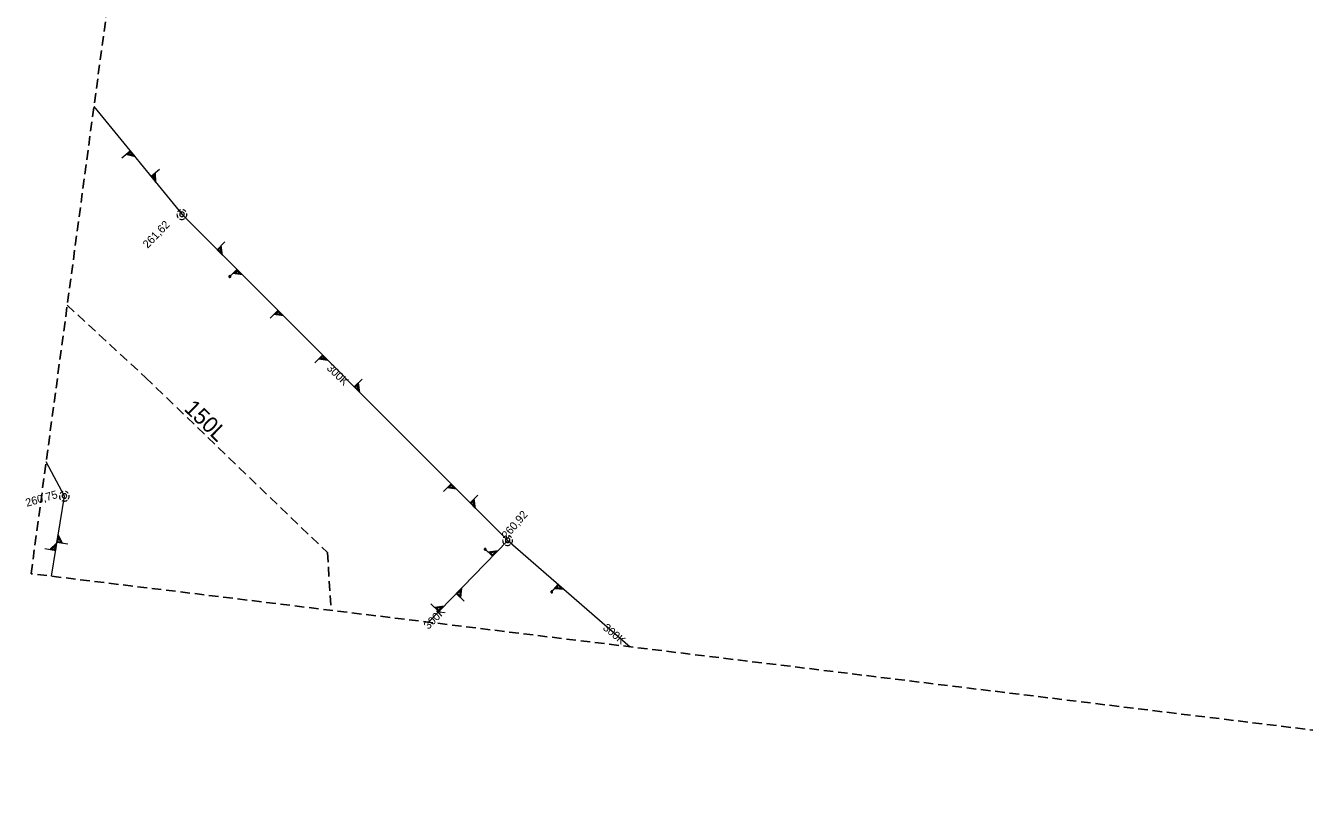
# Model space of a CAD drawing. Extents: x -743212 to -743020, y -1051380 to -1051228.
# Drawn here: x -743212.3 to -743084.5, y -1051380.3 to -1051304 of the extents above; entities that cross this region are included whole.
import ezdxf

# ---------------------------------------------------------------- set-up
doc = ezdxf.new("R2010")
doc.units = 0
doc.header["$LTSCALE"] = 0.32
doc.linetypes.add('MEDIUM_DASHED', pattern=[4.5, 3, -1.5])
for name, color, linetype, lineweight in [('1', 7, 'MEDIUM_DASHED', 25), ('18', 7, 'Continuous', 13), ('20', 7, 'Continuous', 13), ('8', 7, 'Continuous', 13)]:
    doc.layers.add(name, color=color, linetype=linetype, lineweight=lineweight)

msp = doc.modelspace()

# ---------------------------------------------------------------- linework, layer by layer
at = {"layer": '1'}
msp.add_lwpolyline([(-743035.828, -1051380.323), (-743211.786, -1051358.847), (-743211.788, -1051358.847), (-743211.79, -1051358.846), (-743211.791, -1051358.845), (-743211.793, -1051358.844), (-743211.794, -1051358.842), (-743211.794, -1051358.84), (-743211.795, -1051358.838), (-743211.795, -1051358.836), (-743194.164, -1051227.732), (-743194.163, -1051227.73), (-743194.162, -1051227.729), (-743194.161, -1051227.727), (-743194.16, -1051227.726), (-743194.158, -1051227.725), (-743194.157, -1051227.724), (-743194.155, -1051227.724), (-743194.153, -1051227.724), (-743020.025, -1051242.759)], dxfattribs=at)
at = {"layer": '18'}
for points in [[(-743202.739, -1051317.244), (-743201.889, -1051316.551), (-743201.403, -1051317.148), (-743202.337, -1051316.916)], [(-743202.214, -1051316.881), (-743201.892, -1051316.618), (-743201.534, -1051317.057), (-743202.215, -1051316.881)], [(-743202.119, -1051316.864), (-743201.894, -1051316.68), (-743201.659, -1051316.968), (-743202.12, -1051316.863)], [(-743198.954, -1051318.422), (-743199.804, -1051319.114), (-743199.317, -1051319.712), (-743199.356, -1051318.749)], [(-743199.415, -1051318.863), (-743199.738, -1051319.126), (-743199.381, -1051319.564), (-743199.414, -1051318.863)], [(-743199.451, -1051318.953), (-743199.676, -1051319.136), (-743199.442, -1051319.424), (-743199.451, -1051318.952)], [(-743196.863, -1051322.446), (-743196.934, -1051322.474), (-743197, -1051322.513), (-743197.061, -1051322.561), (-743197.112, -1051322.618), (-743197.136, -1051322.652)], [(-743196.321, -1051322.629), (-743196.372, -1051322.571), (-743196.429, -1051322.521), (-743196.495, -1051322.48), (-743196.566, -1051322.451), (-743196.615, -1051322.437)], [(-743197.208, -1051322.838), (-743197.213, -1051322.915), (-743197.208, -1051322.992), (-743197.191, -1051323.067), (-743197.163, -1051323.138), (-743197.122, -1051323.204), (-743197.107, -1051323.226)], [(-743196.95, -1051323.355), (-743196.88, -1051323.386), (-743196.804, -1051323.405), (-743196.728, -1051323.412), (-743196.652, -1051323.407), (-743196.576, -1051323.39), (-743196.505, -1051323.362), (-743196.445, -1051323.327)], [(-743196.326, -1051323.215), (-743196.286, -1051323.15), (-743196.255, -1051323.08), (-743196.235, -1051323.005), (-743196.228, -1051322.929), (-743196.233, -1051322.852), (-743196.239, -1051322.817)], [(-743192.414, -1051325.664), (-743193.189, -1051326.438), (-743192.645, -1051326.984), (-743192.78, -1051326.03)], [(-743192.828, -1051326.149), (-743193.122, -1051326.443), (-743192.723, -1051326.843), (-743192.827, -1051326.148)], [(-743192.854, -1051326.242), (-743193.06, -1051326.447), (-743192.798, -1051326.71), (-743192.855, -1051326.241)], [(-743191.99, -1051329.191), (-743191.215, -1051328.417), (-743190.671, -1051328.962), (-743191.624, -1051328.825)], [(-743191.506, -1051328.777), (-743191.211, -1051328.483), (-743190.811, -1051328.884), (-743191.506, -1051328.778)], [(-743191.413, -1051328.751), (-743191.206, -1051328.545), (-743190.943, -1051328.808), (-743191.414, -1051328.751)], [(-743187.889, -1051333.294), (-743187.113, -1051332.519), (-743186.569, -1051333.064), (-743187.522, -1051332.928)], [(-743187.403, -1051332.88), (-743187.109, -1051332.586), (-743186.709, -1051332.986), (-743187.404, -1051332.88)], [(-743183.437, -1051337.752), (-743182.661, -1051336.977), (-743182.117, -1051337.522), (-743183.07, -1051337.386)], [(-743182.951, -1051337.338), (-743182.657, -1051337.044), (-743182.257, -1051337.444), (-743182.952, -1051337.338)], [(-743178.706, -1051339.393), (-743179.481, -1051340.167), (-743178.937, -1051340.713), (-743179.072, -1051339.759)], [(-743179.12, -1051339.878), (-743179.414, -1051340.172), (-743179.015, -1051340.572), (-743179.119, -1051339.877)], [(-743179.146, -1051339.971), (-743179.352, -1051340.176), (-743179.09, -1051340.439), (-743179.147, -1051339.97)], [(-743208.622, -1051350.627), (-743208.693, -1051350.655), (-743208.76, -1051350.694), (-743208.82, -1051350.742), (-743208.871, -1051350.799), (-743208.895, -1051350.833)], [(-743208.081, -1051350.81), (-743208.131, -1051350.752), (-743208.189, -1051350.702), (-743208.254, -1051350.661), (-743208.325, -1051350.632), (-743208.374, -1051350.618)], [(-743170.577, -1051350.632), (-743169.801, -1051349.857), (-743169.257, -1051350.402), (-743170.21, -1051350.266)], [(-743170.091, -1051350.218), (-743169.797, -1051349.924), (-743169.397, -1051350.324), (-743170.092, -1051350.218)], [(-743208.967, -1051351.019), (-743208.973, -1051351.096), (-743208.968, -1051351.173), (-743208.951, -1051351.248), (-743208.922, -1051351.319), (-743208.882, -1051351.385), (-743208.866, -1051351.407)], [(-743208.709, -1051351.536), (-743208.639, -1051351.567), (-743208.564, -1051351.586), (-743208.488, -1051351.593), (-743208.411, -1051351.588), (-743208.336, -1051351.571), (-743208.264, -1051351.543), (-743208.204, -1051351.508)], [(-743208.086, -1051351.396), (-743208.045, -1051351.331), (-743208.014, -1051351.261), (-743207.995, -1051351.186), (-743207.987, -1051351.11), (-743207.992, -1051351.033), (-743207.998, -1051350.998)], [(-743167.118, -1051350.999), (-743167.893, -1051351.773), (-743167.349, -1051352.319), (-743167.484, -1051351.365)], [(-743167.532, -1051351.484), (-743167.826, -1051351.778), (-743167.427, -1051352.178), (-743167.531, -1051351.483)], [(-743167.558, -1051351.577), (-743167.764, -1051351.782), (-743167.502, -1051352.045), (-743167.559, -1051351.576)], [(-743210.422, -1051356.342), (-743209.34, -1051356.516), (-743209.218, -1051355.755), (-743209.911, -1051356.424)], [(-743209.786, -1051356.392), (-743209.376, -1051356.459), (-743209.286, -1051355.901), (-743209.787, -1051356.392)], [(-743209.696, -1051356.359), (-743209.409, -1051356.406), (-743209.35, -1051356.039), (-743209.696, -1051356.36)], [(-743208.135, -1051355.904), (-743209.217, -1051355.729), (-743209.095, -1051354.969), (-743208.646, -1051355.821)], [(-743208.755, -1051355.753), (-743209.166, -1051355.687), (-743209.076, -1051355.128), (-743208.754, -1051355.753)], [(-743208.83, -1051355.693), (-743209.118, -1051355.647), (-743209.058, -1051355.28), (-743208.831, -1051355.694)], [(-743164.647, -1051355.449), (-743164.652, -1051355.526), (-743164.647, -1051355.603), (-743164.63, -1051355.678), (-743164.602, -1051355.749), (-743164.561, -1051355.815), (-743164.546, -1051355.837)], [(-743164.302, -1051355.057), (-743164.373, -1051355.085), (-743164.44, -1051355.124), (-743164.5, -1051355.172), (-743164.551, -1051355.229), (-743164.575, -1051355.263)], [(-743164.389, -1051355.966), (-743164.319, -1051355.997), (-743164.244, -1051356.016), (-743164.168, -1051356.023), (-743164.091, -1051356.018), (-743164.016, -1051356.001), (-743163.944, -1051355.973), (-743163.884, -1051355.938)], [(-743163.761, -1051355.24), (-743163.811, -1051355.182), (-743163.869, -1051355.132), (-743163.934, -1051355.091), (-743164.005, -1051355.062), (-743164.054, -1051355.048)], [(-743163.766, -1051355.826), (-743163.725, -1051355.761), (-743163.694, -1051355.691), (-743163.674, -1051355.616), (-743163.667, -1051355.54), (-743163.672, -1051355.463), (-743163.678, -1051355.428)], [(-743166.466, -1051356.337), (-743165.679, -1051357.099), (-743165.143, -1051356.545), (-743166.094, -1051356.697)], [(-743165.973, -1051356.743), (-743165.674, -1051357.032), (-743165.281, -1051356.625), (-743165.975, -1051356.742)], [(-743165.881, -1051356.767), (-743165.671, -1051356.97), (-743165.413, -1051356.703), (-743165.882, -1051356.768)], [(-743168.508, -1051361.599), (-743169.296, -1051360.837), (-743168.76, -1051360.284), (-743168.88, -1051361.239)], [(-743168.93, -1051361.121), (-743169.229, -1051360.832), (-743168.836, -1051360.425), (-743168.93, -1051361.122)], [(-743168.958, -1051361.029), (-743169.167, -1051360.827), (-743168.909, -1051360.559), (-743168.959, -1051361.03)], [(-743159.81, -1051360.739), (-743159.092, -1051359.912), (-743158.511, -1051360.417), (-743159.471, -1051360.349)], [(-743159.356, -1051360.292), (-743159.083, -1051359.978), (-743158.656, -1051360.349), (-743159.357, -1051360.293)], [(-743159.265, -1051360.26), (-743159.074, -1051360.039), (-743158.793, -1051360.283), (-743159.266, -1051360.259)], [(-743171.817, -1051361.871), (-743171.029, -1051362.633), (-743170.493, -1051362.079), (-743171.444, -1051362.231)], [(-743171.324, -1051362.277), (-743171.025, -1051362.566), (-743170.632, -1051362.16), (-743171.325, -1051362.276)], [(-743171.231, -1051362.301), (-743171.022, -1051362.504), (-743170.764, -1051362.237), (-743171.232, -1051362.302)]]:
    msp.add_lwpolyline(points, dxfattribs=at)
for points in [[(-743196.478, -1051322.898), (-743196.485, -1051322.846), (-743196.502, -1051322.796), (-743196.531, -1051322.752), (-743196.569, -1051322.715), (-743196.614, -1051322.688), (-743196.664, -1051322.672), (-743196.716, -1051322.667), (-743196.767, -1051322.674), (-743196.816, -1051322.693), (-743196.86, -1051322.723), (-743196.896, -1051322.762), (-743196.922, -1051322.807), (-743196.936, -1051322.858), (-743196.94, -1051322.91), (-743196.931, -1051322.962), (-743196.911, -1051323.01), (-743196.88, -1051323.053), (-743196.841, -1051323.088), (-743196.794, -1051323.112), (-743196.744, -1051323.126), (-743196.691, -1051323.128), (-743196.64, -1051323.118), (-743196.592, -1051323.096), (-743196.549, -1051323.064), (-743196.517, -1051323.024), (-743196.493, -1051322.977), (-743196.48, -1051322.926)], [(-743191.857, -1051329.191), (-743191.838, -1051329.163), (-743191.83, -1051329.131), (-743191.833, -1051329.097), (-743191.849, -1051329.068), (-743191.873, -1051329.045), (-743191.904, -1051329.032), (-743191.938, -1051329.031), (-743191.97, -1051329.041), (-743191.995, -1051329.063), (-743192.012, -1051329.091), (-743192.019, -1051329.124), (-743192.012, -1051329.157), (-743191.995, -1051329.186), (-743191.969, -1051329.208), (-743191.937, -1051329.218), (-743191.904, -1051329.216), (-743191.873, -1051329.203)], [(-743191.876, -1051329.171), (-743191.86, -1051329.147), (-743191.855, -1051329.119), (-743191.864, -1051329.092), (-743191.881, -1051329.071), (-743191.907, -1051329.058), (-743191.935, -1051329.058), (-743191.961, -1051329.068), (-743191.98, -1051329.089), (-743191.99, -1051329.115), (-743191.987, -1051329.143), (-743191.973, -1051329.168), (-743191.951, -1051329.185), (-743191.922, -1051329.191), (-743191.896, -1051329.185)], [(-743187.311, -1051332.853), (-743187.105, -1051332.648), (-743186.842, -1051332.911)], [(-743182.859, -1051337.311), (-743182.653, -1051337.106), (-743182.39, -1051337.369)], [(-743208.238, -1051351.079), (-743208.244, -1051351.027), (-743208.262, -1051350.977), (-743208.29, -1051350.933), (-743208.328, -1051350.896), (-743208.373, -1051350.869), (-743208.423, -1051350.853), (-743208.475, -1051350.848), (-743208.527, -1051350.855), (-743208.576, -1051350.874), (-743208.62, -1051350.904), (-743208.655, -1051350.943), (-743208.681, -1051350.988), (-743208.696, -1051351.039), (-743208.699, -1051351.091), (-743208.691, -1051351.143), (-743208.67, -1051351.191), (-743208.64, -1051351.234), (-743208.6, -1051351.269), (-743208.554, -1051351.293), (-743208.503, -1051351.307), (-743208.451, -1051351.309), (-743208.399, -1051351.299), (-743208.351, -1051351.277), (-743208.309, -1051351.245), (-743208.276, -1051351.205), (-743208.252, -1051351.158), (-743208.24, -1051351.107)], [(-743169.999, -1051350.191), (-743169.793, -1051349.986), (-743169.53, -1051350.249)], [(-743163.918, -1051355.509), (-743163.924, -1051355.457), (-743163.941, -1051355.407), (-743163.97, -1051355.363), (-743164.008, -1051355.326), (-743164.053, -1051355.299), (-743164.103, -1051355.283), (-743164.155, -1051355.278), (-743164.206, -1051355.285), (-743164.255, -1051355.304), (-743164.299, -1051355.334), (-743164.335, -1051355.373), (-743164.361, -1051355.418), (-743164.375, -1051355.469), (-743164.379, -1051355.521), (-743164.37, -1051355.573), (-743164.35, -1051355.621), (-743164.32, -1051355.664), (-743164.28, -1051355.699), (-743164.233, -1051355.723), (-743164.183, -1051355.737), (-743164.13, -1051355.739), (-743164.079, -1051355.729), (-743164.031, -1051355.707), (-743163.989, -1051355.675), (-743163.956, -1051355.635), (-743163.932, -1051355.588), (-743163.919, -1051355.537)], [(-743166.332, -1051356.334), (-743166.36, -1051356.316), (-743166.393, -1051356.308), (-743166.426, -1051356.312), (-743166.455, -1051356.328), (-743166.478, -1051356.352), (-743166.49, -1051356.384), (-743166.491, -1051356.418), (-743166.48, -1051356.449), (-743166.459, -1051356.475), (-743166.429, -1051356.492), (-743166.396, -1051356.497), (-743166.364, -1051356.491), (-743166.335, -1051356.472), (-743166.314, -1051356.447), (-743166.304, -1051356.415), (-743166.306, -1051356.381), (-743166.319, -1051356.35)], [(-743166.35, -1051356.355), (-743166.374, -1051356.34), (-743166.402, -1051356.336), (-743166.429, -1051356.344), (-743166.451, -1051356.363), (-743166.462, -1051356.388), (-743166.463, -1051356.417), (-743166.452, -1051356.442), (-743166.431, -1051356.462), (-743166.404, -1051356.47), (-743166.376, -1051356.467), (-743166.351, -1051356.453), (-743166.335, -1051356.431), (-743166.33, -1051356.402), (-743166.336, -1051356.374)], [(-743159.677, -1051360.73), (-743159.66, -1051360.701), (-743159.654, -1051360.668), (-743159.66, -1051360.635), (-743159.677, -1051360.607), (-743159.703, -1051360.586), (-743159.735, -1051360.575), (-743159.769, -1051360.576), (-743159.8, -1051360.589), (-743159.824, -1051360.612), (-743159.839, -1051360.641), (-743159.843, -1051360.675), (-743159.834, -1051360.708), (-743159.815, -1051360.735), (-743159.787, -1051360.755), (-743159.755, -1051360.763), (-743159.722, -1051360.759), (-743159.692, -1051360.744)], [(-743159.697, -1051360.711), (-743159.683, -1051360.686), (-743159.68, -1051360.659), (-743159.691, -1051360.632), (-743159.71, -1051360.612), (-743159.736, -1051360.601), (-743159.764, -1051360.603), (-743159.79, -1051360.615), (-743159.807, -1051360.637), (-743159.814, -1051360.664), (-743159.81, -1051360.692), (-743159.794, -1051360.716), (-743159.771, -1051360.731), (-743159.742, -1051360.735), (-743159.716, -1051360.727)]]:
    msp.add_lwpolyline(points, close=True, dxfattribs=at)
at = {"layer": '20'}
for p, q in [((-743205.511, -1051312.108), (-743196.71, -1051322.909)), ((-743205.511, -1051312.108), (-743196.71, -1051322.909)), ((-743196.71, -1051322.909), (-743164.149, -1051355.52)), ((-743196.71, -1051322.909), (-743164.149, -1051355.52)), ((-743208.469, -1051351.09), (-743210.29, -1051347.647)), ((-743208.469, -1051351.09), (-743210.29, -1051347.647)), ((-743209.759, -1051359.095), (-743208.469, -1051351.09)), ((-743209.759, -1051359.095), (-743208.469, -1051351.09)), ((-743172.06, -1051363.696), (-743164.149, -1051355.52)), ((-743172.06, -1051363.696), (-743164.149, -1051355.52)), ((-743164.149, -1051355.52), (-743151.888, -1051366.158)), ((-743164.149, -1051355.52), (-743151.888, -1051366.158))]:
    msp.add_line(p, q, dxfattribs=at)
at = {"layer": '8', "linetype": 'MEDIUM_DASHED', "lineweight": 25}
msp.add_lwpolyline([(-743208.184, -1051331.988), (-743200.35, -1051339.23), (-743182.17, -1051356.73), (-743181.803, -1051362.507)], dxfattribs=at)

# ---------------------------------------------------------------- texts
at = {"layer": '1'}
for s, height, rotation, p in [('261,62', 0.8, 46, (-743200.145, -1051326.356)), ('300K', 0.8, 316, (-743182.308, -1051338.355)), ('150L', 1.6, 316, (-743196.583, -1051342.45)), ('260,75', 0.8, 16, (-743212.223, -1051352.16)), ('260,92', 0.8, 49, (-743164.233, -1051355.439)), ('300K', 0.8, 45, (-743172.076, -1051364.47)), ('300K', 0.8, 320, (-743154.696, -1051364.363))]:
    msp.add_text(s, height=height, rotation=rotation, dxfattribs=at).set_placement(p)

doc.saveas('drawing.dxf')
